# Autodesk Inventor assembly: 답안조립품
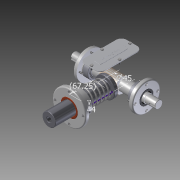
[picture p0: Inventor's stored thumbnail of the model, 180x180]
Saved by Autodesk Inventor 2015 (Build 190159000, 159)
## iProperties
Created: 2016-02
Part Number: 답안조립품
Document SubType Name: Assembly
Designer: Administrator
Mass: 8191.32 g
Surface Area: 4241.85 cm^2
Volume: 1855.5 cm^3
Density: 4.41461 g/cm^3
Author: Administrator
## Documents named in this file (15)
- C:\Users\Administrator\Desktop\360220V1015\답안조립품.iam
- C:\Users\Administrator\Desktop\360220V1015\본체.ipt
- C:\Users\Administrator\Desktop\360220V1015\슬라이드 커버.ipt
- C:\Users\Administrator\Desktop\360220V1015\축 커버.ipt
- C:\Users\Administrator\Desktop\360220V1015\볼트 M4x0.7.ipt
- C:\Users\Administrator\Desktop\360220V1015\상부커버.ipt
- C:\Users\Administrator\Desktop\360220V1015\육각머리볼트 M4.ipt
- C:\Users\Administrator\Desktop\360220V1015\오일실.ipt
- 오일실.ipt
- C:\Users\Administrator\Desktop\360220V1015\베어링 6205.ipt
- 베어링 6205.ipt
- C:\Users\Administrator\Desktop\360220V1015\부시.ipt
- C:\Users\Administrator\Desktop\360220V1015\편심축.ipt
- C:\Users\Administrator\Desktop\360220V1015\가변스프링.ipt
- C:\Users\Administrator\Desktop\360220V1015\슬라이드.ipt
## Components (13 placed, 2 different names)
1. 가변스프링:1
2. M4x0.7:1
3. M4x0.7:2
4. M4x0.7:3
5. M4x0.7:4
6. M4x0.7:5
7. M4x0.7:6
8. M4x0.7:7
9. M4x0.7:8
10. M4x0.7:9
11. M4x0.7:10
12. M4x0.7:11
13. M4x0.7:12
